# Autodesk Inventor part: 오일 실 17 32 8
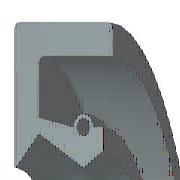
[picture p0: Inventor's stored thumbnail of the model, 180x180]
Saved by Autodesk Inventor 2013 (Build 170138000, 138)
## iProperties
IsCustomPart: 0
Created: 2018-09
Part Number: 오일 실 17 32 8
Material: 고무
Description: 오일-실
Document SubType Name: Modeling
Standard: KS B 2804
Standards Organization: KS
Language: ko-KR
Size Designation: D - 17 32 8
Categories: <MemberInstance><Categories><Category DisplayName="샤프트 부품" InternalName="7f7aeb1f-a693-4053-b835-cee3144e0d98" Mnemonic="SHFT"><Category DisplayName="실링" Intern
Density: 0.93 g/cm^3
Mass: 2.28027 g
Surface Area: 32.1224 cm^2
Volume: 2.45191 cm^3
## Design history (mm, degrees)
revolve "본체" stored, may be unused: angle "d17" = 90 deg
revolve "스프링1" stored, may be unused: angle "d18" = 90 deg
body "Solid1"
sketch "스케치1"
  geometry: L1 (0, 16)-(8, 16); L2 (8, 14.25)-(1.75, 14.25); L3 (1.75, 10.25)-(4.9, 8.5); L4 (4.9, 8.5)-(0, 8.5); L5 (0, 0)-(9.586, 0) reference; L6 (4.9, 8.5)-(6.3, 9.375); L7 (0, 18)-(0, -3) reference; L8 (-1.941, 0)-(11.507, 0) reference; L9 (4.2, 10.6)-(1.75, 11.21); L10 (1.75, 11.21)-(1.75, 14.25); L11 (0, 16)-(0, 8.588); L12 (4.9, 8.5)-(0, 8.5); L13 (1.75, 10.25)-(0.152, 8.528); L14 (8, 16)-(8, 14.25); L15 (5.6, 10.6)-(6.3, 10.6); L16 (6.3, 10.6)-(6.3, 9.375); C1 r 0.455 at (4.9, 10.6); A1 r 0.7 centre (4.9, 10.6) between (5.6, 10.6) and (4.2, 10.6); A2 r 0.088 centre (0.088, 8.588) between (0, 8.588) and (0.152, 8.528); 1 further point
  constraints: 28 end point, 5 horizontal alignment, 5 point on line, 4 point on circle, 4 vertical alignment, 3 centre point, 3 tangent, 2 collinear, 2 horizontal, 2 perpendicular, 1 coincident, 1 parallel
  dimensions: "d0" = 32 diameter of L1 L5 (= SD2); "d1" = 1.75 distance of L1.end L2.start (= SD); "d2" = 0.91 diameter of C1 (= SPDI); "d3" = 1.4 diameter of A1 (= SPDA); "d4" = 17 diameter of L3.end L5 (= NND); "d5" = 20.5 diameter of L3.start L5 (= TKDM); "d7" = 22.42 diameter of L9.end L5 (= TKDM + 0.24 x SWDT); "d8" = 1.75 distance between parallel lines of L11 L10 (= SD); "d9" = 4.9 distance from line of L11 C1.centre (= SPDST); "d10" = 21.2 diameter of C1.centre L5 (= HLDM); "d11" = 0.0875 radius of A2 (= 0.25 x LAB); "d12" = 6.3 distance between parallel lines of L11 L16 (= SDI); "d13" = 18.75 diameter of L6.end L5 (= ABDM); "d14" = 8 distance from line of L11 L1.end (= SWDT)
fillet "모깎기1" dims "d6" = 0.3 (= RR)
other parameters: "SD2" = 32 [user parameter; used in 1 equation term], "SWDT" = 8 [user parameter; used in 2 equation terms], "RR" = 0.3 [user parameter; used in 1 equation term], "SD" = 1.75 [user parameter; used in 2 equation terms], "NND" = 17 [user parameter; used in 1 equation term], "SPDA" = 1.4 [user parameter; used in 1 equation term], "SPDI" = 0.91 [user parameter; used in 1 equation term], "TKDM" = 20.5 [user parameter; used in 2 equation terms], "HLDM" = 21.2 [user parameter; used in 1 equation term], "ABDM" = 18.75 [user parameter; used in 1 equation term], "SDI" = 6.3 [user parameter; used in 1 equation term], "SPDST" = 4.9 [user parameter; used in 1 equation term], "LAB" = 0.35 [user parameter; used in 1 equation term], "d15" = 0, "d16" = 0, "d19" = 0
